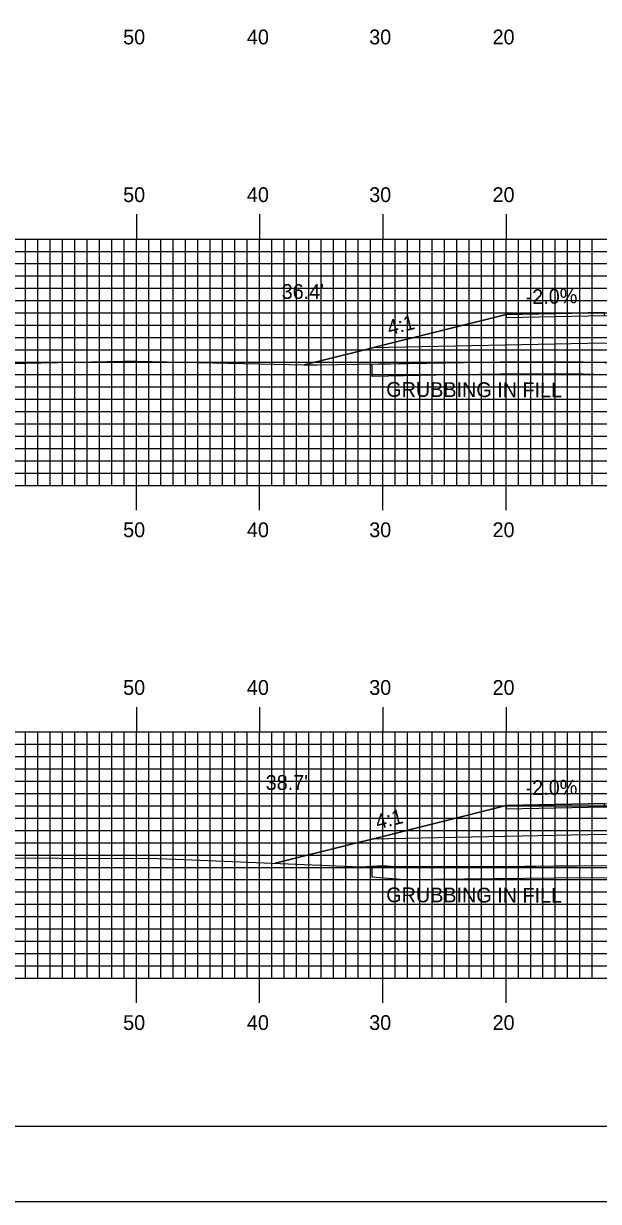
# Model space of a CAD drawing. Extents: x 1814522 to 1814865, y 442591 to 442811.
# Drawn here: x 1814628.4 to 1814675, y 442590.5 to 442686.2 of the extents above; entities that cross this region are included whole.
import ezdxf

# ---------------------------------------------------------------- set-up
doc = ezdxf.new("R2010")
doc.units = 0
for name, color, linetype in [('ANNOTATION', 7, 'Continuous'), ('BORDER', 7, 'Continuous'), ('D_Roadway_Centerline', 7, 'Continuous'), ('D_Roadway_Edge_Shoulder', 7, 'Continuous'), ('D_Roadway_SlopeLines', 7, 'Continuous'), ('D_Roadway_SubGrade', 7, 'Continuous'), ('D_Text_Standard', 7, 'Continuous'), ('GRUBBING IN FILL', 7, 'Continuous'), ('H_V ANNOTATION', 7, 'Continuous'), ('MAJOR', 7, 'Continuous'), ('MINOR', 7, 'Continuous'), ('PLOT BOUNDARY', 7, 'Continuous'), ('S_Roadway_Centerline', 7, 'Continuous')]:
    doc.layers.add(name, color=color, linetype=linetype)

msp = doc.modelspace()

# ---------------------------------------------------------------- linework, layer by layer
at = {"layer": 'BORDER'}
msp.add_lwpolyline([(1814537.908, 442596.665), (1814857.908, 442596.665), (1814857.908, 442806.665), (1814537.908, 442806.665)], close=True, dxfattribs=at)
at = {"layer": 'D_Roadway_Centerline'}
for points in [[(1814651.128, 442658.443), (1814655.508, 442659.538), (1814656.638, 442659.82), (1814667.508, 442662.538), (1814675.508, 442662.698), (1814687.508, 442662.122), (1814699.508, 442661.546), (1814707.508, 442661.162), (1814719.884, 442658.068), (1814723.884, 442657.068), (1814724.096, 442657.174), (1814725.346, 442657.716), (1814726.596, 442658.092), (1814727.846, 442658.302), (1814729.096, 442658.346)], [(1814648.778, 442617.995), (1814655.508, 442619.677), (1814656.638, 442619.96), (1814667.508, 442622.677), (1814675.508, 442622.837), (1814687.508, 442622.261), (1814699.508, 442621.685), (1814707.508, 442621.301), (1814719.884, 442618.207), (1814724.865, 442616.962)]]:
    msp.add_lwpolyline(points, dxfattribs=at)
at = {"layer": 'D_Roadway_Edge_Shoulder'}
for points in [[(1814675.508, 442662.698), (1814667.508, 442662.538), (1814667.508, 442662.288), (1814675.508, 442662.448)], [(1814675.508, 442622.837), (1814667.508, 442622.677), (1814667.508, 442622.427), (1814675.508, 442622.587)]]:
    msp.add_lwpolyline(points, close=True, dxfattribs=at)
at = {"layer": 'D_Roadway_SlopeLines'}
for points in [[(1814667.508, 442662.538), (1814656.638, 442659.82), (1814655.508, 442659.538), (1814651.128, 442658.443)], [(1814667.508, 442622.677), (1814656.638, 442619.96), (1814655.508, 442619.677), (1814648.778, 442617.995)]]:
    msp.add_lwpolyline(points, dxfattribs=at)
at = {"layer": 'D_Roadway_SubGrade'}
for points in [[(1814675.508, 442660.198), (1814656.638, 442659.82), (1814667.508, 442662.538), (1814667.508, 442662.288), (1814675.508, 442662.448), (1814687.508, 442661.872), (1814699.508, 442661.296), (1814707.508, 442660.912), (1814707.508, 442661.162), (1814719.884, 442658.068), (1814699.508, 442659.046), (1814687.508, 442659.622)], [(1814675.508, 442620.337), (1814656.638, 442619.96), (1814667.508, 442622.677), (1814667.508, 442622.427), (1814675.508, 442622.587), (1814687.508, 442622.011), (1814699.508, 442621.435), (1814707.508, 442621.051), (1814707.508, 442621.301), (1814719.884, 442618.207), (1814699.508, 442619.185), (1814687.508, 442619.761)]]:
    msp.add_lwpolyline(points, close=True, dxfattribs=at)
at = {"layer": 'GRUBBING IN FILL'}
for points in [[(1814656.638, 442658.518), (1814659.608, 442658.568), (1814667.028, 442658.692), (1814672.934, 442658.724), (1814678.897, 442658.53), (1814684.86, 442658.336), (1814687.508, 442658.289), (1814687.508, 442657.289), (1814684.835, 442657.336), (1814678.883, 442657.53), (1814672.93, 442657.724), (1814667.028, 442657.691), (1814661.833, 442657.605), (1814656.638, 442657.518)], [(1814656.638, 442658.518), (1814659.608, 442658.568), (1814667.028, 442658.692), (1814672.934, 442658.724), (1814678.897, 442658.53), (1814684.86, 442658.336), (1814687.508, 442658.289), (1814687.508, 442657.289), (1814684.835, 442657.336), (1814678.883, 442657.53), (1814672.93, 442657.724), (1814667.028, 442657.691), (1814661.833, 442657.605), (1814656.638, 442657.518)], [(1814656.638, 442617.761), (1814658.431, 442617.728), (1814666.601, 442617.728), (1814676.646, 442617.802), (1814684.916, 442617.767), (1814687.508, 442617.751), (1814687.508, 442616.751), (1814684.907, 442616.767), (1814679.401, 442616.8), (1814673.892, 442616.804), (1814666.585, 442616.728), (1814659.277, 442616.652), (1814656.638, 442616.879)], [(1814656.638, 442617.761), (1814658.431, 442617.728), (1814666.601, 442617.728), (1814676.646, 442617.802), (1814684.916, 442617.767), (1814687.508, 442617.751), (1814687.508, 442616.751), (1814684.907, 442616.767), (1814679.401, 442616.8), (1814673.892, 442616.804), (1814666.585, 442616.728), (1814659.277, 442616.652), (1814656.638, 442616.879)]]:
    msp.add_lwpolyline(points, close=True, dxfattribs=at)
at = {"layer": 'MAJOR'}
for p, q in [((1814637.508, 442670.669), (1814637.508, 442668.665)), ((1814647.508, 442670.669), (1814647.508, 442668.665)), ((1814657.508, 442670.669), (1814657.508, 442668.665)), ((1814667.508, 442670.669), (1814667.508, 442668.665)), ((1814547.508, 442668.665), (1814827.508, 442668.665)), ((1814547.508, 442668.665), (1814827.508, 442668.665)), ((1814637.508, 442648.665), (1814637.508, 442668.665)), ((1814647.508, 442648.665), (1814647.508, 442668.665)), ((1814657.508, 442648.665), (1814657.508, 442668.665)), ((1814667.508, 442648.665), (1814667.508, 442668.665)), ((1814547.508, 442663.665), (1814827.508, 442663.665)), ((1814547.508, 442658.665), (1814827.508, 442658.665)), ((1814547.508, 442653.665), (1814827.508, 442653.665)), ((1814547.508, 442648.665), (1814827.508, 442648.665)), ((1814547.508, 442648.665), (1814827.508, 442648.665)), ((1814637.508, 442646.661), (1814637.508, 442648.665)), ((1814647.508, 442646.661), (1814647.508, 442648.665)), ((1814657.508, 442646.661), (1814657.508, 442648.665)), ((1814667.508, 442646.661), (1814667.508, 442648.665)), ((1814637.508, 442630.669), (1814637.508, 442628.665)), ((1814647.508, 442630.669), (1814647.508, 442628.665)), ((1814657.508, 442630.669), (1814657.508, 442628.665)), ((1814667.508, 442630.669), (1814667.508, 442628.665)), ((1814547.508, 442628.665), (1814827.508, 442628.665)), ((1814547.508, 442628.665), (1814827.508, 442628.665)), ((1814637.508, 442608.665), (1814637.508, 442628.665)), ((1814647.508, 442608.665), (1814647.508, 442628.665)), ((1814657.508, 442608.665), (1814657.508, 442628.665)), ((1814667.508, 442608.665), (1814667.508, 442628.665)), ((1814547.508, 442623.665), (1814827.508, 442623.665)), ((1814547.508, 442618.665), (1814827.508, 442618.665)), ((1814547.508, 442613.665), (1814827.508, 442613.665)), ((1814547.508, 442608.665), (1814827.508, 442608.665)), ((1814547.508, 442608.665), (1814827.508, 442608.665)), ((1814637.508, 442606.661), (1814637.508, 442608.665)), ((1814647.508, 442606.661), (1814647.508, 442608.665)), ((1814657.508, 442606.661), (1814657.508, 442608.665)), ((1814667.508, 442606.661), (1814667.508, 442608.665))]:
    msp.add_line(p, q, dxfattribs=at)
at = {"layer": 'MINOR'}
for p, q in [((1814628.508, 442648.665), (1814628.508, 442668.665)), ((1814629.508, 442648.665), (1814629.508, 442668.665)), ((1814630.508, 442648.665), (1814630.508, 442668.665)), ((1814631.508, 442648.665), (1814631.508, 442668.665)), ((1814632.508, 442648.665), (1814632.508, 442668.665)), ((1814633.508, 442648.665), (1814633.508, 442668.665)), ((1814634.508, 442648.665), (1814634.508, 442668.665)), ((1814635.508, 442648.665), (1814635.508, 442668.665)), ((1814636.508, 442648.665), (1814636.508, 442668.665)), ((1814638.508, 442648.665), (1814638.508, 442668.665)), ((1814639.508, 442648.665), (1814639.508, 442668.665)), ((1814640.508, 442648.665), (1814640.508, 442668.665)), ((1814641.508, 442648.665), (1814641.508, 442668.665)), ((1814642.508, 442648.665), (1814642.508, 442668.665)), ((1814643.508, 442648.665), (1814643.508, 442668.665)), ((1814644.508, 442648.665), (1814644.508, 442668.665)), ((1814645.508, 442648.665), (1814645.508, 442668.665)), ((1814646.508, 442648.665), (1814646.508, 442668.665)), ((1814648.508, 442648.665), (1814648.508, 442668.665)), ((1814649.508, 442648.665), (1814649.508, 442668.665)), ((1814650.508, 442648.665), (1814650.508, 442668.665)), ((1814651.508, 442648.665), (1814651.508, 442668.665)), ((1814652.508, 442648.665), (1814652.508, 442668.665)), ((1814653.508, 442648.665), (1814653.508, 442668.665)), ((1814654.508, 442648.665), (1814654.508, 442668.665)), ((1814655.508, 442648.665), (1814655.508, 442668.665)), ((1814656.508, 442648.665), (1814656.508, 442668.665)), ((1814658.508, 442648.665), (1814658.508, 442668.665)), ((1814659.508, 442648.665), (1814659.508, 442668.665)), ((1814660.508, 442648.665), (1814660.508, 442668.665)), ((1814661.508, 442648.665), (1814661.508, 442668.665)), ((1814662.508, 442648.665), (1814662.508, 442668.665)), ((1814663.508, 442648.665), (1814663.508, 442668.665)), ((1814664.508, 442648.665), (1814664.508, 442668.665)), ((1814665.508, 442648.665), (1814665.508, 442668.665)), ((1814666.508, 442648.665), (1814666.508, 442668.665)), ((1814668.508, 442648.665), (1814668.508, 442668.665)), ((1814669.508, 442648.665), (1814669.508, 442668.665)), ((1814670.508, 442648.665), (1814670.508, 442668.665)), ((1814671.508, 442648.665), (1814671.508, 442668.665)), ((1814672.508, 442648.665), (1814672.508, 442668.665)), ((1814673.508, 442648.665), (1814673.508, 442668.665)), ((1814674.508, 442648.665), (1814674.508, 442668.665)), ((1814547.508, 442667.665), (1814827.508, 442667.665)), ((1814547.508, 442666.665), (1814827.508, 442666.665)), ((1814547.508, 442665.665), (1814827.508, 442665.665)), ((1814547.508, 442664.665), (1814827.508, 442664.665)), ((1814547.508, 442662.665), (1814827.508, 442662.665)), ((1814547.508, 442661.665), (1814827.508, 442661.665)), ((1814547.508, 442660.665), (1814827.508, 442660.665)), ((1814547.508, 442659.665), (1814827.508, 442659.665)), ((1814547.508, 442657.665), (1814827.508, 442657.665)), ((1814547.508, 442656.665), (1814827.508, 442656.665)), ((1814547.508, 442655.665), (1814827.508, 442655.665)), ((1814547.508, 442654.665), (1814827.508, 442654.665)), ((1814547.508, 442652.665), (1814827.508, 442652.665)), ((1814547.508, 442651.665), (1814827.508, 442651.665)), ((1814547.508, 442650.665), (1814827.508, 442650.665)), ((1814547.508, 442649.665), (1814827.508, 442649.665)), ((1814628.508, 442608.665), (1814628.508, 442628.665)), ((1814629.508, 442608.665), (1814629.508, 442628.665)), ((1814630.508, 442608.665), (1814630.508, 442628.665)), ((1814631.508, 442608.665), (1814631.508, 442628.665)), ((1814632.508, 442608.665), (1814632.508, 442628.665)), ((1814633.508, 442608.665), (1814633.508, 442628.665)), ((1814634.508, 442608.665), (1814634.508, 442628.665)), ((1814635.508, 442608.665), (1814635.508, 442628.665)), ((1814636.508, 442608.665), (1814636.508, 442628.665)), ((1814638.508, 442608.665), (1814638.508, 442628.665)), ((1814639.508, 442608.665), (1814639.508, 442628.665)), ((1814640.508, 442608.665), (1814640.508, 442628.665)), ((1814641.508, 442608.665), (1814641.508, 442628.665)), ((1814642.508, 442608.665), (1814642.508, 442628.665)), ((1814643.508, 442608.665), (1814643.508, 442628.665)), ((1814644.508, 442608.665), (1814644.508, 442628.665)), ((1814645.508, 442608.665), (1814645.508, 442628.665)), ((1814646.508, 442608.665), (1814646.508, 442628.665)), ((1814648.508, 442608.665), (1814648.508, 442628.665)), ((1814649.508, 442608.665), (1814649.508, 442628.665)), ((1814650.508, 442608.665), (1814650.508, 442628.665)), ((1814651.508, 442608.665), (1814651.508, 442628.665)), ((1814652.508, 442608.665), (1814652.508, 442628.665)), ((1814653.508, 442608.665), (1814653.508, 442628.665)), ((1814654.508, 442608.665), (1814654.508, 442628.665)), ((1814655.508, 442608.665), (1814655.508, 442628.665)), ((1814656.508, 442608.665), (1814656.508, 442628.665)), ((1814658.508, 442608.665), (1814658.508, 442628.665)), ((1814659.508, 442608.665), (1814659.508, 442628.665)), ((1814660.508, 442608.665), (1814660.508, 442628.665)), ((1814661.508, 442608.665), (1814661.508, 442628.665)), ((1814662.508, 442608.665), (1814662.508, 442628.665)), ((1814663.508, 442608.665), (1814663.508, 442628.665)), ((1814664.508, 442608.665), (1814664.508, 442628.665)), ((1814665.508, 442608.665), (1814665.508, 442628.665)), ((1814666.508, 442608.665), (1814666.508, 442628.665)), ((1814668.508, 442608.665), (1814668.508, 442628.665)), ((1814669.508, 442608.665), (1814669.508, 442628.665)), ((1814670.508, 442608.665), (1814670.508, 442628.665)), ((1814671.508, 442608.665), (1814671.508, 442628.665)), ((1814672.508, 442608.665), (1814672.508, 442628.665)), ((1814673.508, 442608.665), (1814673.508, 442628.665)), ((1814674.508, 442608.665), (1814674.508, 442628.665)), ((1814547.508, 442627.665), (1814827.508, 442627.665)), ((1814547.508, 442626.665), (1814827.508, 442626.665)), ((1814547.508, 442625.665), (1814827.508, 442625.665)), ((1814547.508, 442624.665), (1814827.508, 442624.665)), ((1814547.508, 442622.665), (1814827.508, 442622.665)), ((1814547.508, 442621.665), (1814827.508, 442621.665)), ((1814547.508, 442620.665), (1814827.508, 442620.665)), ((1814547.508, 442619.665), (1814827.508, 442619.665)), ((1814547.508, 442617.665), (1814827.508, 442617.665)), ((1814547.508, 442616.665), (1814827.508, 442616.665)), ((1814547.508, 442615.665), (1814827.508, 442615.665)), ((1814547.508, 442614.665), (1814827.508, 442614.665)), ((1814547.508, 442612.665), (1814827.508, 442612.665)), ((1814547.508, 442611.665), (1814827.508, 442611.665)), ((1814547.508, 442610.665), (1814827.508, 442610.665)), ((1814547.508, 442609.665), (1814827.508, 442609.665))]:
    msp.add_line(p, q, dxfattribs=at)
at = {"layer": 'PLOT BOUNDARY'}
msp.add_lwpolyline([(1814521.721, 442590.547), (1814861.721, 442590.547), (1814861.721, 442810.547), (1814521.721, 442810.547)], close=True, dxfattribs=at)
at = {"layer": 'S_Roadway_Centerline'}
for points in [[(1814547.508, 442659.883), (1814554.061, 442660.02), (1814565.763, 442659.35), (1814571.631, 442659.132), (1814576.17, 442658.826), (1814587.171, 442658.471), (1814590.92, 442658.569), (1814604.613, 442658.158), (1814607.228, 442658.032), (1814627.098, 442658.565), (1814636.481, 442658.76), (1814637.549, 442658.763), (1814651.161, 442658.442), (1814652.188, 442658.444), (1814667.028, 442658.692), (1814669.782, 442658.646), (1814672.934, 442658.724), (1814684.86, 442658.336), (1814697.632, 442658.11), (1814701.767, 442658.129), (1814707.313, 442658.166), (1814719.862, 442658.297), (1814727.24, 442658.436), (1814735.311, 442658.047)], [(1814623.209, 442618.44), (1814639.265, 442618.387), (1814640.725, 442618.321), (1814655.687, 442617.715), (1814657.548, 442617.804), (1814659.315, 442617.653), (1814673.887, 442617.804), (1814679.405, 442617.8), (1814690.427, 442617.734), (1814699.743, 442617.522), (1814705.658, 442617.284), (1814716.869, 442617.095), (1814722.958, 442616.967), (1814730.994, 442616.946), (1814738.896, 442616.855)]]:
    msp.add_lwpolyline(points, dxfattribs=at)

# ---------------------------------------------------------------- texts
at = {"layer": 'ANNOTATION'}
for s, rotation, p in [('-2.0%', 1.14576, (1814669.114, 442663.37)), ('4:1', 14.03624, (1814658.034, 442660.844)), ('-2.0%', 1.14576, (1814669.114, 442623.51)), ('4:1', 14.03624, (1814657.082, 442620.736))]:
    msp.add_text(s, height=1.2, rotation=rotation, dxfattribs=at).set_placement(p)
at = {"layer": 'D_Text_Standard'}
for s, p in [("36.4'", (1814649.303, 442663.802)), ("38.7'", (1814648.005, 442623.949))]:
    msp.add_text(s, height=1.2, dxfattribs=at).set_placement(p)
at = {"layer": 'GRUBBING IN FILL'}
for p in [(1814657.785, 442655.859), (1814657.785, 442614.837)]:
    msp.add_text('GRUBBING IN FILL', height=1.2, rotation=359.80532, dxfattribs=at).set_placement(p)
at = {"layer": 'H_V ANNOTATION'}
for s, p in [('50', (1814636.437, 442684.465)), ('40', (1814646.48, 442684.465)), ('30', (1814656.405, 442684.465)), ('20', (1814666.415, 442684.465)), ('50', (1814636.437, 442671.665)), ('40', (1814646.48, 442671.665)), ('30', (1814656.405, 442671.665)), ('20', (1814666.415, 442671.665)), ('50', (1814636.437, 442644.465)), ('40', (1814646.48, 442644.465)), ('30', (1814656.405, 442644.465)), ('20', (1814666.415, 442644.465)), ('50', (1814636.437, 442631.665)), ('40', (1814646.48, 442631.665)), ('30', (1814656.405, 442631.665)), ('20', (1814666.415, 442631.665)), ('50', (1814636.437, 442604.465)), ('40', (1814646.48, 442604.465)), ('30', (1814656.405, 442604.465)), ('20', (1814666.415, 442604.465))]:
    msp.add_text(s, height=1.2, dxfattribs=at).set_placement(p)

doc.saveas('drawing.dxf')
